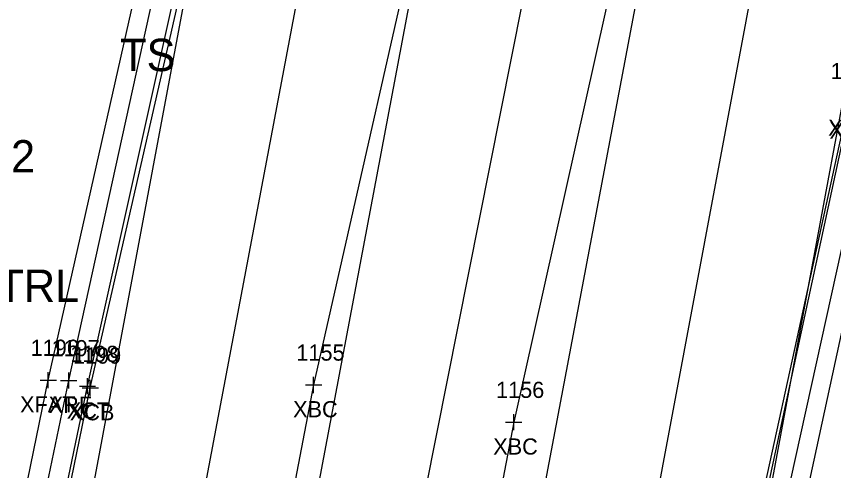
# Model space of a CAD drawing. Extents: x 1683147 to 1683637, y 416837 to 418211.
# Drawn here: x 1683229.7 to 1683280.1, y 417608.4 to 417636.5 of the extents above; entities that cross this region are included whole.
import ezdxf

# ---------------------------------------------------------------- set-up
doc = ezdxf.new("R2010")
doc.units = 0
for name, color, linetype in [('B_A', 7, 'Continuous'), ('B_I', 7, 'Continuous'), ('B_TIC', 7, 'Continuous'), ('BB', 7, 'Continuous'), ('BDC', 7, 'Continuous'), ('BELB', 7, 'Continuous'), ('BF', 7, 'Continuous'), ('BR', 7, 'Continuous'), ('C_A', 7, 'Continuous'), ('C_I', 7, 'Continuous'), ('L_A', 7, 'Continuous')]:
    doc.layers.add(name, color=color, linetype=linetype)

msp = doc.modelspace()

# ---------------------------------------------------------------- linework, layer by layer
at = {"layer": 'B_TIC'}
for p, q in [((1683231.658, 417613.999), (1683231.734, 417613.999)), ((1683232.92, 417613.974), (1683232.996, 417613.974)), ((1683234.077, 417613.621), (1683234.153, 417613.621)), ((1683248.039, 417613.702), (1683248.114, 417613.702)), ((1683234.252, 417613.515), (1683234.327, 417613.515)), ((1683260.397, 417611.397), (1683260.472, 417611.397))]:
    msp.add_line(p, q, dxfattribs=at)
for points in [[(1683231.655, 417613.499), (1683231.655, 417614.499)], [(1683232.917, 417613.474), (1683232.917, 417614.474)], [(1683234.074, 417613.121), (1683234.074, 417614.121)], [(1683248.035, 417613.202), (1683248.035, 417614.202)], [(1683231.155, 417613.999), (1683232.155, 417613.999)], [(1683232.417, 417613.974), (1683233.417, 417613.974)], [(1683233.574, 417613.621), (1683234.574, 417613.621)], [(1683234.248, 417613.014), (1683234.248, 417614.015)], [(1683247.535, 417613.702), (1683248.535, 417613.702)], [(1683233.748, 417613.515), (1683234.748, 417613.515)], [(1683260.393, 417610.897), (1683260.393, 417611.897)], [(1683259.893, 417611.397), (1683260.893, 417611.397)]]:
    msp.add_lwpolyline(points, dxfattribs=at)
at = {"layer": 'BB'}
for points in [[(1683247.534, 417457.283), (1683256.806, 417505.82), (1683275.504, 417603.185), (1683284.507, 417651.57)], [(1683240.224, 417455.825), (1683249.612, 417504.3), (1683268.309, 417601.755), (1683277.362, 417650.167)], [(1683233.056, 417454.423), (1683242.375, 417502.873), (1683260.963, 417600.277), (1683270.09, 417648.672)], [(1683225.817, 417452.979), (1683235.185, 417501.44), (1683252.981, 417597.315), (1683262.91, 417647.271)], [(1683218.639, 417451.571), (1683227.942, 417499.995), (1683246.282, 417596.559), (1683255.565, 417645.821)], [(1683211.398, 417450.232), (1683220.685, 417498.601), (1683239.091, 417595.537), (1683248.339, 417644.482)], [(1683204.248, 417448.864), (1683213.453, 417497.213), (1683232.034, 417594.621), (1683241.123, 417643.096)]]:
    msp.add_lwpolyline(points, dxfattribs=at)
at = {"layer": 'BDC'}
for points in [[(1683248.051, 417455.436), (1683253.896, 417491.851), (1683257.783, 417514.592), (1683265.936, 417559.114), (1683272.886, 417593.685), (1683281.07, 417631.095), (1683286.315, 417653.984)], [(1683248.206, 417455.394), (1683254.065, 417491.776), (1683257.952, 417514.755), (1683266.138, 417559.151), (1683273.116, 417593.593), (1683281.173, 417630.923), (1683286.527, 417654.075)], [(1683204.26, 417446.59), (1683207.746, 417469.989), (1683213.462, 417505.801), (1683221.311, 417549.93), (1683228.046, 417584.722), (1683234.074, 417613.621), (1683241.065, 417645.18)], [(1683204.523, 417446.635), (1683207.943, 417470.136), (1683213.692, 417505.86), (1683221.542, 417549.946), (1683228.342, 417584.807), (1683234.248, 417613.515), (1683241.392, 417644.923)]]:
    msp.add_lwpolyline(points, dxfattribs=at)
at = {"layer": 'BELB'}
for points in [[(1683269.206, 417650.948), (1683260.393, 417611.397), (1683256.447, 417590.785), (1683246.822, 417543.339), (1683241.399, 417511.39), (1683234.932, 417474.067), (1683231.661, 417452.147)], [(1683255.821, 417648.166), (1683248.035, 417613.702), (1683243.06, 417587.805), (1683234.781, 417546.02), (1683228.274, 417508.761), (1683222.317, 417473.758), (1683218.863, 417449.537)]]:
    msp.add_lwpolyline(points, dxfattribs=at)
at = {"layer": 'BF'}
for points in [[(1683250.624, 417454.9), (1683256.47, 417491.459), (1683260.265, 417514.98), (1683268.347, 417558.692), (1683275.679, 417593.916), (1683283.544, 417630.285), (1683288.924, 417653.565)], [(1683201.852, 417446.968), (1683205.241, 417469.957), (1683210.957, 417505.098), (1683219.149, 417550.319), (1683225.494, 417584.011), (1683231.655, 417613.999), (1683238.79, 417645.736)]]:
    msp.add_lwpolyline(points, dxfattribs=at)
at = {"layer": 'BR'}
for points in [[(1683248.519, 417448.641), (1683249.479, 417455.186), (1683255.278, 417491.444), (1683259.237, 417514.807), (1683267.406, 417559.099), (1683274.406, 417593.753), (1683282.508, 417630.53), (1683290.526, 417665.488)], [(1683201.249, 417434.944), (1683203.019, 417446.95), (1683206.413, 417469.882), (1683212.207, 417505.421), (1683220.042, 417550.002), (1683226.73, 417584.319), (1683232.917, 417613.974), (1683239.772, 417645.191), (1683242.155, 417655.448)]]:
    msp.add_lwpolyline(points, dxfattribs=at)

# ---------------------------------------------------------------- texts
at = {"layer": 'B_A'}
for s, p in [('XCB', (1683279.806, 417629.095)), ('XCT', (1683279.893, 417628.923)), ('XFAT', (1683229.911, 417611.999)), ('XRF', (1683231.677, 417611.974)), ('XCT', (1683232.794, 417611.621)), ('XBC', (1683246.772, 417611.702)), ('XCB', (1683232.985, 417611.515)), ('XBC', (1683259.129, 417609.397))]:
    msp.add_text(s, height=1, dxfattribs=at).set_placement(p)
at = {"layer": 'B_I'}
for s, p in [('1140', (1683279.964, 417632.595)), ('1196', (1683230.564, 417615.499)), ('1197', (1683231.854, 417615.474)), ('1198', (1683233.011, 417615.121)), ('1155', (1683246.973, 417615.202)), ('1199', (1683233.182, 417615.015)), ('1156', (1683259.303, 417612.897))]:
    msp.add_text(s, height=1, dxfattribs=at).set_placement(p)
at = {"layer": 'C_A'}
msp.add_text('HVCTRL', height=2, dxfattribs=at).set_placement((1683222.866, 417618.827))
at = {"layer": 'C_I'}
msp.add_text('122', height=2, dxfattribs=at).set_placement((1683226.377, 417626.827))
at = {"layer": 'L_A'}
msp.add_text('TS', height=2, dxfattribs=at).set_placement((1683236.087, 417633.091))

doc.saveas('drawing.dxf')
